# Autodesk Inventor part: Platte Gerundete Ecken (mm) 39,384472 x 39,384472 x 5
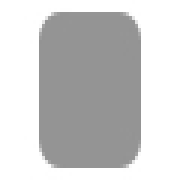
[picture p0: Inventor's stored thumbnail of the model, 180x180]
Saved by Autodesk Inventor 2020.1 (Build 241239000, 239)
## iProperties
Created: 2019-01
Part Number: Platte Gerundete Ecken (mm) 39,384472 x 39,384472 x 5
Material: Stahl, weich
Document SubType Name: Modeling
Designer: lutzd
Language: de-DE
Size Designation: 5 x 39,384472 x 39,384472
Categories: <MemberInstance><Categories><Category DisplayName="Sonstige Bauteile" InternalName="5aa15e00-363f-49f2-933f-16f664388e3f" Mnemonic="OTHER"><Category DisplayName
Mass: 60.0398 g
Surface Area: 38.0412 cm^2
Volume: 7.64838 cm^3
Density: 7.85 g/cm^3
Appearance: Semi-Polished(8)
IsCustomPart: 1
Author: lutzd
Revision Number: -
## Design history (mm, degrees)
sketch "Sketch1"
  geometry: L1 (0, 20.175)-(0, -21.446); L2 (-20.203, 0)-(20.169, 0); L3 (-19.692, 19.692)-(19.692, 19.692); L4 (19.692, 19.692)-(19.692, -19.692); L5 (19.692, -19.692)-(-19.692, -19.692); L6 (-19.692, -19.692)-(-19.692, 19.692); 1 further point
  constraints: 12 end point, 2 horizontal, 2 parallel, 2 point on line, 1 perpendicular, 1 vertical
  dimensions: "d0" = 39.38447 distance between parallel lines of L5 L3 (= height); "d1" = 19.69224 distance between parallel lines of L2 L3 (= 0.5 x height); "d2" = 39.38447 distance between parallel lines of L6 L4 (= width); "d3" = 19.69224 distance between parallel lines of L6 L1 (= 0.5 x width)
extrude "Extrusion1" new body sketch "Sketch1" distance "d4" = 5 (= thickness); taper "d5" = 0 deg
fillet "Fillet1" dims "d6" = 5 (= fillet), "d7" = 0, "fillet" = 5 [user parameter; used in 1 equation term]
chamfer "Chamfer1" distance "d8" = 0 (computed from chamfer); stored, may be unused: second distance "d9" = 2, angle "d10" = 45 deg; dims "d11" = 0, "chamfer" = 0 [user parameter; used in 1 equation term]
body "Solid1"
other parameters: "thickness" = 5 [user parameter; used in 1 equation term], "width" = 39.38447 [user parameter; used in 2 equation terms], "height" = 39.38447 [user parameter; used in 2 equation terms]
